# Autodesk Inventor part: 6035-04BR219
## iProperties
Author: Ron Crain
Shininess: 27.0
Angle Display Precision: 2
Document Length Units: 11272
Document Angle Units: 11286
Document Time Units: 11279
Document Mass Units: 11290
Document Length Units Precision: 4
Document Angle Units Precision: 2
Compacted: True
PropertySet Name: _Private Model Information
Created: 2002-03
Part Number: 6035-04BR219
Material: Brass, Soft Yellow
Description: Ultrasert II, 4-40 x .219
Vendor: DODGE
Document SubType Name: Modeling
Designer: Ron Crain
Control State: 0
Master: False
Checked Out: False
PropertySet Name: Design Tracking Control
Density: 0.0
Volumn: 0.0
Area: 0.0
PropertySet Name: Model Information
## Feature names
1. Revolution1
2. Revolution3
3. Revolution2
